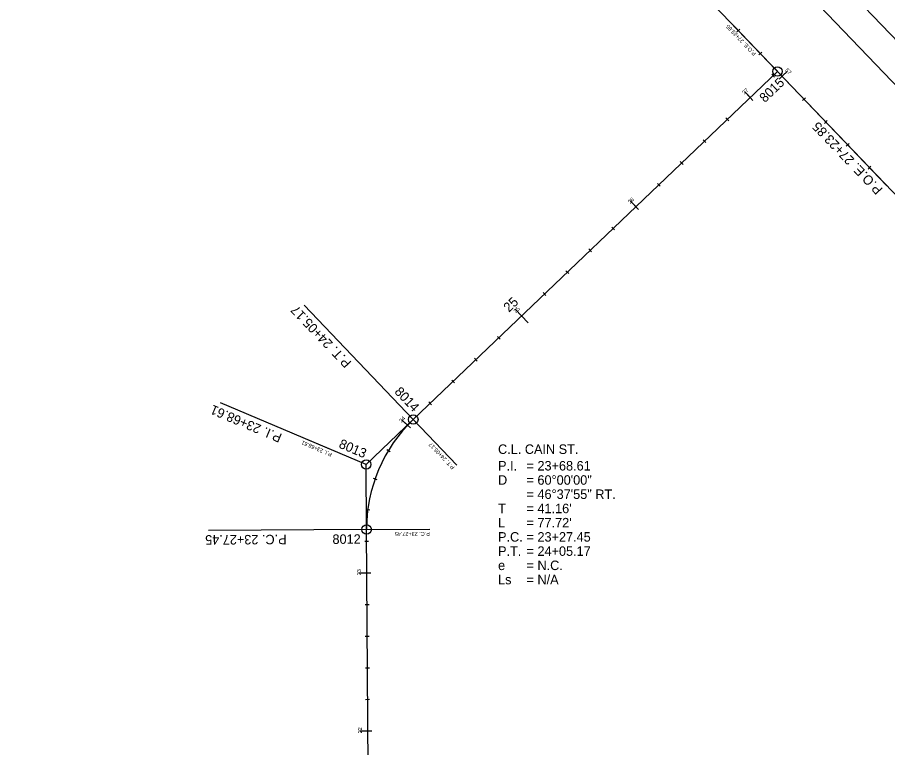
# Model space of a CAD drawing. Extents: x 1708585 to 1714116, y 541444 to 545437.
# Drawn here: x 1710887 to 1711438, y 544448 to 544909 of the extents above; entities that cross this region are included whole.
import ezdxf

# ---------------------------------------------------------------- set-up
doc = ezdxf.new("R2010")
doc.units = 0
for name, color, linetype in [('CL_Highway_2', 7, 'Continuous'), ('CL_Highway_2_40_Sta', 7, 'Continuous'), ('CL_Highway_2_Sta', 7, 'Continuous'), ('CL_Railroad', 7, 'Continuous'), ('CL_XS_2', 7, 'Continuous'), ('CL_XS_2_40_PText', 7, 'Continuous'), ('CL_XS_2_40_Sta', 7, 'Continuous'), ('CL_XS_2_PText', 7, 'Continuous'), ('CL_XS_2_Sta', 7, 'Continuous'), ('CL_XS_2_Tangent', 7, 'Continuous'), ('CurveData_100', 7, 'Continuous'), ('Point_CL_XS_2', 7, 'Continuous'), ('Point_Number', 7, 'Continuous')]:
    doc.layers.add(name, color=color, linetype=linetype)

msp = doc.modelspace()

# ---------------------------------------------------------------- linework, layer by layer
at = {"layer": 'CL_Highway_2'}
msp.add_line((1710887.1, 545378.25), (1711975.18, 544239.94), dxfattribs=at)
at = {"layer": 'CL_Highway_2_40_Sta'}
for points in [[(1711344.05, 544902.02), (1711342.24, 544900.29)], [(1711357.87, 544887.56), (1711356.06, 544885.83)], [(1711372.59, 544873.97), (1711368.98, 544870.51)], [(1711385.51, 544858.64), (1711383.7, 544856.92)], [(1711399.33, 544844.19), (1711397.52, 544842.46)], [(1711413.15, 544829.73), (1711411.34, 544828)], [(1711426.97, 544815.27), (1711425.16, 544813.54)]]:
    msp.add_lwpolyline(points, dxfattribs=at)
at = {"layer": 'CL_Highway_2_Sta'}
msp.add_lwpolyline([(1711374.04, 544875.35), (1711370.79, 544872.24)], dxfattribs=at)
at = {"layer": 'CL_Railroad'}
for p, q in [((1710938.24, 545423.05), (1713356.67, 542892.99)), ((1710923.78, 545409.23), (1713342.21, 542879.17))]:
    msp.add_line(p, q, dxfattribs=at)
at = {"layer": 'CL_XS_2'}
for p, q in [((1711137.49, 544655.1), (1711367.86, 544875.3)), ((1711109.92, 544258.06), (1711107.98, 544585.51))]:
    msp.add_line(p, q, dxfattribs=at)
msp.add_arc((1711203.47, 544586.07), 95.49, 133.7074, 180.3393, dxfattribs=at)
at = {"layer": 'CL_XS_2_40_PText'}
for points in [[(1711367.86, 544875.3), (1711340.22, 544904.22)], [(1711137.49, 544655.1), (1711165.13, 544626.19)], [(1711107.74, 544626.66), (1711070.91, 544642.28)], [(1711107.98, 544585.51), (1711147.98, 544585.74)]]:
    msp.add_lwpolyline(points, dxfattribs=at)
at = {"layer": 'CL_XS_2_40_Sta'}
for points in [[(1711366.13, 544877.11), (1711369.58, 544873.5)], [(1711366.13, 544877.11), (1711369.58, 544873.5)], [(1711364.21, 544873.55), (1711365.94, 544871.74)], [(1711348.89, 544860.63), (1711352.35, 544857.02)], [(1711335.3, 544845.91), (1711337.02, 544844.1)], [(1711320.84, 544832.09), (1711322.57, 544830.28)], [(1711306.38, 544818.27), (1711308.11, 544816.46)], [(1711291.92, 544804.45), (1711293.65, 544802.64)], [(1711276.6, 544791.53), (1711280.06, 544787.92)], [(1711263.01, 544776.81), (1711264.74, 544775)], [(1711248.55, 544762.99), (1711250.28, 544761.18)], [(1711234.09, 544749.17), (1711235.82, 544747.36)], [(1711219.64, 544735.35), (1711221.36, 544733.54)], [(1711204.31, 544722.44), (1711207.77, 544718.82)], [(1711190.72, 544707.71), (1711192.45, 544705.91)], [(1711176.26, 544693.89), (1711177.99, 544692.09)], [(1711161.81, 544680.07), (1711163.53, 544678.27)], [(1711147.35, 544666.25), (1711149.08, 544664.45)], [(1711132.03, 544653.14), (1711135.68, 544649.72)], [(1711120.72, 544636.18), (1711122.85, 544634.88)], [(1711112.11, 544617.88), (1711114.47, 544617.05)], [(1711107.49, 544598.18), (1711109.97, 544597.87)], [(1711106.78, 544578.05), (1711109.28, 544578.07)], [(1711105.64, 544558.04), (1711110.64, 544558.07)], [(1711107.01, 544538.05), (1711109.51, 544538.07)], [(1711107.13, 544518.05), (1711109.63, 544518.07)], [(1711107.25, 544498.05), (1711109.75, 544498.07)], [(1711107.37, 544478.05), (1711109.87, 544478.07)], [(1711106.24, 544458.05), (1711111.24, 544458.08)]]:
    msp.add_lwpolyline(points, dxfattribs=at)
at = {"layer": 'CL_XS_2_PText'}
for points in [[(1711367.86, 544875.3), (1711436.95, 544803.01)], [(1711137.49, 544655.1), (1711068.39, 544727.39)], [(1711107.74, 544626.66), (1711015.67, 544665.7)], [(1711107.98, 544585.51), (1711007.98, 544584.91)]]:
    msp.add_lwpolyline(points, dxfattribs=at)
at = {"layer": 'CL_XS_2_Sta'}
for points in [[(1711347.16, 544862.44), (1711350.62, 544858.82)], [(1711274.88, 544793.34), (1711278.33, 544789.73)], [(1711201.9, 544724.97), (1711210.19, 544716.29)], [(1711130.21, 544654.85), (1711133.85, 544651.43)], [(1711103.14, 544558.03), (1711108.14, 544558.06)], [(1711103.74, 544458.03), (1711108.74, 544458.06)]]:
    msp.add_lwpolyline(points, dxfattribs=at)
at = {"layer": 'CL_XS_2_Tangent'}
for p, q in [((1711107.74, 544626.66), (1711137.49, 544655.1)), ((1711107.98, 544585.51), (1711107.74, 544626.66))]:
    msp.add_line(p, q, dxfattribs=at)
at = {"layer": 'Point_CL_XS_2'}
for centre in [(1711367.86, 544875.3), (1711137.49, 544655.1), (1711107.74, 544626.66), (1711107.98, 544585.51)]:
    msp.add_circle(centre, 3, dxfattribs=at)

# ---------------------------------------------------------------- texts
at = {"layer": 'CL_Highway_2_40_Sta'}
msp.add_text('57', height=2.5, rotation=313.7074, dxfattribs=at).set_placement((1711372.49, 544875.89))
at = {"layer": 'CL_XS_2_40_PText'}
for s, rotation, p in [('P.O.E. 27+23.85', 133.7074, (1711354.56, 544886.68)), ('P.I. 23+68.61', 157.0233, (1711086.41, 544633.81)), ('P.T. 24+05.17', 133.7074, (1711163.86, 544624.98)), ('P.C. 23+27.45', 180.3393, (1711147.99, 544583.99))]:
    msp.add_text(s, height=2.5, rotation=rotation, dxfattribs=at).set_placement(p)
at = {"layer": 'CL_XS_2_40_Sta'}
for s, rotation, p in [('27', 43.7074, (1711346.97, 544860.52)), ('26', 43.7074, (1711274.64, 544791.39)), ('25', 43.7074, (1711202.39, 544722.33)), ('24', 46.8079, (1711130.12, 544652.93)), ('23', 90.3393, (1711104.4, 544556.57)), ('22', 90.3393, (1711105, 544456.57))]:
    msp.add_text(s, height=2.5, rotation=rotation, dxfattribs=at).set_placement(p)
at = {"layer": 'CL_XS_2_PText'}
for s, rotation, p in [('P.O.E. 27+23.85', 133.7074, (1711434.79, 544800.94)), ('P.T. 24+05.17', 133.7074, (1711098.76, 544691.28)), ('P.I. 23+68.61', 157.0233, (1711054.95, 544645.79)), ('P.C. 23+27.45', 180.3393, (1711057.37, 544582.21))]:
    msp.add_text(s, height=6, rotation=rotation, dxfattribs=at).set_placement(p)
at = {"layer": 'CL_XS_2_Sta'}
msp.add_text('25', height=6, rotation=43.7074, dxfattribs=at).set_placement((1711198.03, 544722.65))
at = {"layer": 'CurveData_100'}
for s, p in [('C.L. CAIN ST.', (1711191.13, 544633.33)), ('P.I.', (1711191.13, 544622.83)), ('= 23+68.61', (1711209.13, 544622.83)), ('D', (1711191.13, 544613.83)), ('= 60%%d00\'00"', (1711209.13, 544613.83)), ('= 46%%d37\'55" RT.', (1711209.13, 544604.83)), ('T', (1711191.13, 544595.83)), ("= 41.16'", (1711209.13, 544595.83)), ('L', (1711191.13, 544586.83)), ("= 77.72'", (1711209.13, 544586.83)), ('P.C.', (1711191.13, 544577.83)), ('= 23+27.45', (1711209.13, 544577.83)), ('P.T.', (1711191.13, 544568.83)), ('= 24+05.17', (1711209.13, 544568.83)), ('e', (1711191.13, 544559.83)), ('= N.C.', (1711209.13, 544559.83)), ('Ls', (1711191.13, 544550.83)), ('= N/A', (1711209.13, 544550.83))]:
    msp.add_text(s, height=6, dxfattribs=at).set_placement(p)
at = {"layer": 'Point_Number'}
for s, rotation, p in [('8015', 43.7074, (1711359.89, 544855.23)), ('8014', 313.7074, (1711125.2, 544672.3)), ('8013', 337.0233, (1711089.92, 544637.48)), ('8012', 0.3393, (1711086.41, 544576.38))]:
    msp.add_text(s, height=6, rotation=rotation, dxfattribs=at).set_placement(p)

doc.saveas('drawing.dxf')
